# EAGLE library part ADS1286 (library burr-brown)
12-Bit Micro Power Sampling ADC
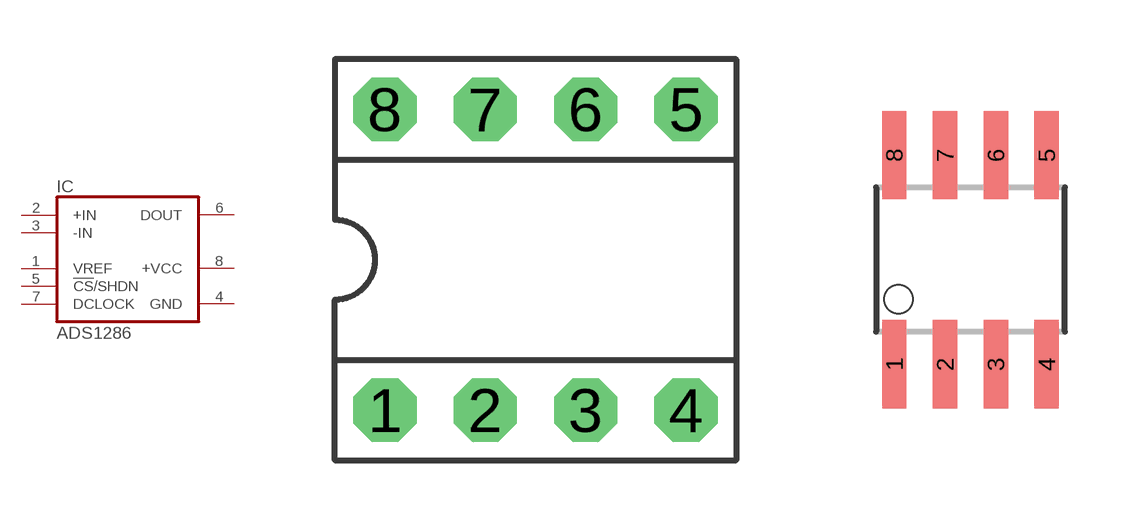
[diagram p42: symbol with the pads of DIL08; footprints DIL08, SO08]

Designator prefix IC

## ADS1286P (MF: TEXAS INSTRUMENT CONNECTORS; MPN: ADS1286P; OC_FARNELL: 1214453; OC_NEWARK: 74C7011)  [DIL08]
1  VREF  in
2  +IN  in
3  -IN  in
4  GND  pwr
5  !CS!/SHDN  in
6  DOUT  out
7  DCLOCK  in
8  +VCC  pwr

## ADS1286U (MF: TEXAS INSTRUMENTS; MPN: ADS1286U; OC_FARNELL: 1106203; OC_NEWARK: 80K5544)  [SO08]
Pads as for DIL08

## Footprint DIL08 (pad centres in mm)
Dual In Line
drill 0.813 pad 1.6 octagon: 1 -3.81,-3.81; 2 -1.27,-3.81; 3 1.27,-3.81; 4 3.81,-3.81; 5 3.81,3.81; 6 1.27,3.81; 7 -1.27,3.81; 8 -3.81,3.81

## Footprint SO08 (pad centres in mm)
Small Outline Package
smd 0.61 x 2.21: 1 -1.905,-2.616; 2 -0.635,-2.616; 3 0.635,-2.616; 4 1.905,-2.616; 5 1.905,2.616; 6 0.635,2.616; 7 -0.635,2.616; 8 -1.905,2.616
